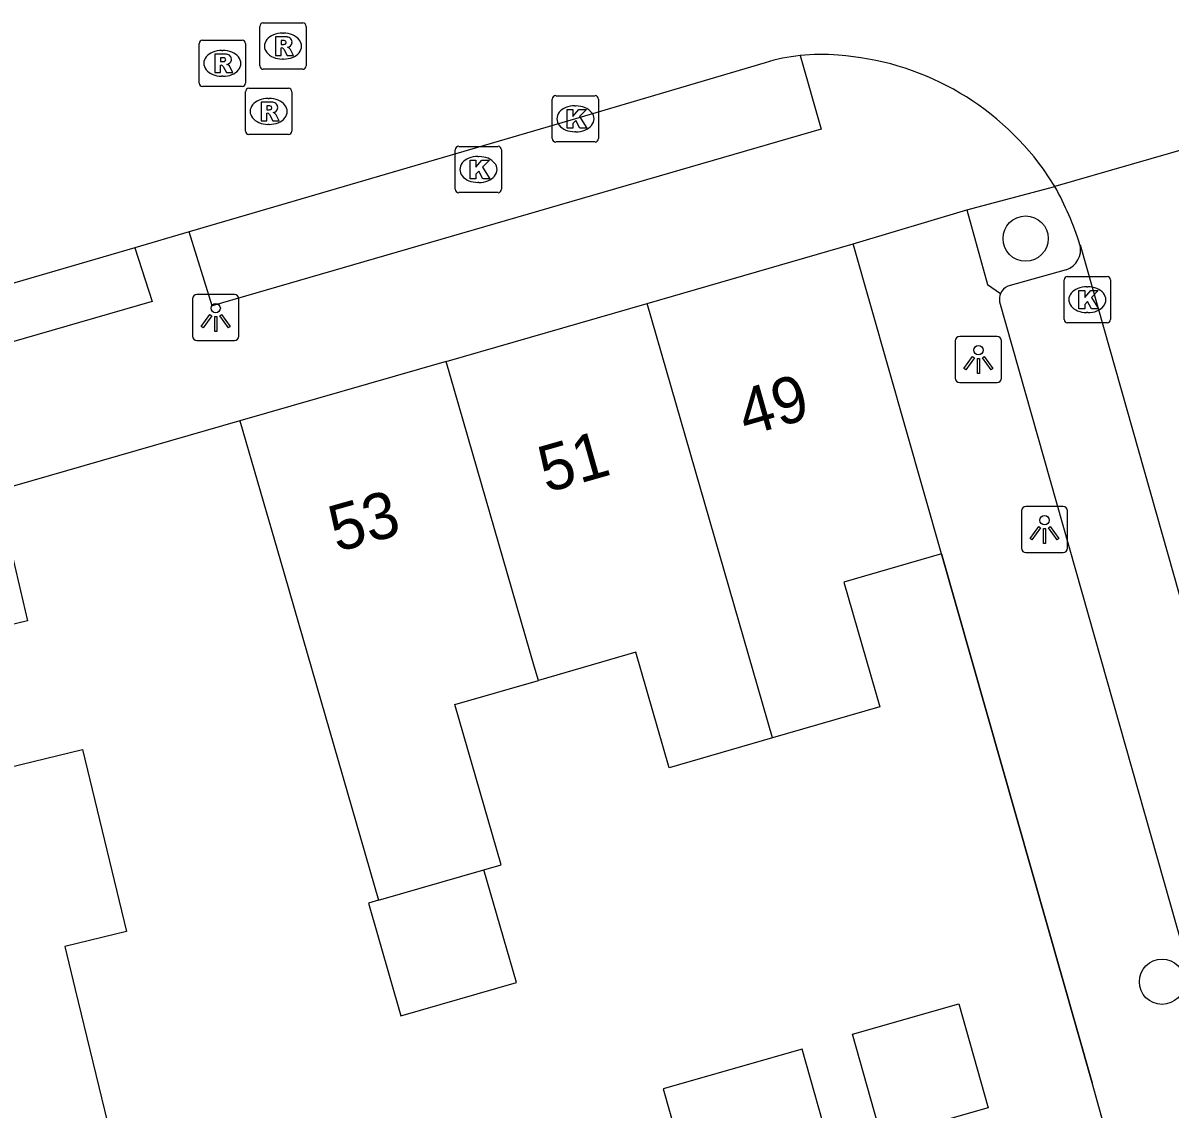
# Model space of a CAD drawing. Extents: x 159718 to 160783, y 383290 to 384030.
# Drawn here: x 160253.65 to 160278.43, y 383556.96 to 383580.41 of the extents above; entities that cross this region are included whole.
import ezdxf

# ---------------------------------------------------------------- set-up
doc = ezdxf.new("R2010")
doc.units = 0
for name, color, linetype in [('IMGEO_Boom', 7, 'Continuous'), ('IMGEO_Kolk', 7, 'Continuous'), ('IMGEO_Lichtpunt', 7, 'Continuous'), ('IMGEO_Muur', 7, 'Continuous'), ('IMGEO_Pand', 7, 'Continuous'), ('IMGEO_Pand_nummerreeks', 7, 'Continuous'), ('IMGEO_Parkeervlak_open', 7, 'Continuous'), ('IMGEO_Rijbaan_lokaal_open', 7, 'Continuous'), ('IMGEO_Rioolput', 7, 'Continuous'), ('IMGEO_Voetpad_open', 7, 'Continuous')]:
    doc.layers.add(name, color=color, linetype=linetype)

msp = doc.modelspace()

# ---------------------------------------------------------------- linework, layer by layer
at = {"layer": 'IMGEO_Boom'}
for centre in [(160275.308, 383575.752), (160278.253, 383559.705)]:
    msp.add_circle(centre, 0.489, dxfattribs=at)
at = {"layer": 'IMGEO_Kolk'}
for p, q in [((160265.083, 383577.911), (160265.083, 383578.763)), ((160265.158, 383578.837), (160266.01, 383578.837)), ((160266.084, 383578.763), (160266.084, 383577.911)), ((160265.571, 383578.617), (160265.596, 383578.617)), ((160265.594, 383578.057), (160265.569, 383578.057)), ((160266.01, 383577.837), (160265.158, 383577.837)), ((160262.988, 383576.817), (160262.988, 383577.669)), ((160263.063, 383577.743), (160263.915, 383577.743)), ((160263.476, 383577.523), (160263.501, 383577.523)), ((160263.989, 383577.669), (160263.989, 383576.817)), ((160263.499, 383576.963), (160263.474, 383576.963)), ((160263.915, 383576.743), (160263.063, 383576.743)), ((160276.139, 383574.006), (160276.139, 383574.858)), ((160276.214, 383574.932), (160277.066, 383574.932)), ((160277.14, 383574.858), (160277.14, 383574.006)), ((160276.627, 383574.712), (160276.652, 383574.712)), ((160276.65, 383574.152), (160276.625, 383574.152)), ((160277.066, 383573.932), (160276.214, 383573.932))]:
    msp.add_line(p, q, dxfattribs=at)
for points in [[(160265.083, 383577.911), (160265.083, 383578.763)], [(160265.158, 383578.837), (160266.01, 383578.837)], [(160266.084, 383578.763), (160266.084, 383577.911)], [(160265.404, 383578.537), (160265.527, 383578.537), (160265.527, 383578.386), (160265.657, 383578.537), (160265.821, 383578.537), (160265.675, 383578.386), (160265.828, 383578.137), (160265.676, 383578.137), (160265.591, 383578.301), (160265.527, 383578.234), (160265.527, 383578.137), (160265.404, 383578.137), (160265.404, 383578.537)], [(160266.01, 383577.837), (160265.158, 383577.837)], [(160262.988, 383576.817), (160262.988, 383577.669)], [(160263.063, 383577.743), (160263.915, 383577.743)], [(160263.989, 383577.669), (160263.989, 383576.817)], [(160263.309, 383577.443), (160263.432, 383577.443), (160263.432, 383577.292), (160263.562, 383577.443), (160263.726, 383577.443), (160263.58, 383577.292), (160263.733, 383577.043), (160263.581, 383577.043), (160263.496, 383577.207), (160263.432, 383577.14), (160263.432, 383577.043), (160263.309, 383577.043), (160263.309, 383577.443)], [(160263.915, 383576.743), (160263.063, 383576.743)], [(160276.139, 383574.006), (160276.139, 383574.858)], [(160276.214, 383574.932), (160277.066, 383574.932)], [(160277.14, 383574.858), (160277.14, 383574.006)], [(160276.46, 383574.632), (160276.583, 383574.632), (160276.583, 383574.481), (160276.713, 383574.632), (160276.877, 383574.632), (160276.731, 383574.481), (160276.884, 383574.232), (160276.732, 383574.232), (160276.647, 383574.396), (160276.583, 383574.329), (160276.583, 383574.232), (160276.46, 383574.232), (160276.46, 383574.632)], [(160277.066, 383573.932), (160276.214, 383573.932)]]:
    msp.add_lwpolyline(points, dxfattribs=at)
for centre, start, end in [((160265.16, 383578.761), 91.552, 178.448), ((160265.16, 383578.761), 91.552, 178.448), ((160266.008, 383578.761), 1.552, 88.448), ((160266.008, 383578.761), 1.552, 88.448), ((160265.16, 383577.913), 181.552, 268.448), ((160265.16, 383577.913), 181.552, 268.448), ((160266.008, 383577.913), 271.552, 358.448), ((160266.008, 383577.913), 271.552, 358.448), ((160263.065, 383577.667), 91.552, 178.448), ((160263.065, 383577.667), 91.552, 178.448), ((160263.913, 383577.667), 1.552, 88.448), ((160263.913, 383577.667), 1.552, 88.448), ((160263.065, 383576.819), 181.552, 268.448), ((160263.065, 383576.819), 181.552, 268.448), ((160263.913, 383576.819), 271.552, 358.448), ((160263.913, 383576.819), 271.552, 358.448), ((160276.216, 383574.856), 91.552, 178.448), ((160276.216, 383574.856), 91.552, 178.448), ((160277.064, 383574.856), 1.552, 88.448), ((160277.064, 383574.856), 1.552, 88.448), ((160276.216, 383574.008), 181.552, 268.448), ((160276.216, 383574.008), 181.552, 268.448), ((160277.064, 383574.008), 271.552, 358.448), ((160277.064, 383574.008), 271.552, 358.448)]:
    msp.add_arc(centre, 0.0765, start, end, dxfattribs=at)
for centre, major_axis, ratio, start_param, end_param in [((160265.57, 383578.337), (-0.387, 0.002), 0.722429, 4.712389, 7.853982), ((160265.595, 383578.337), (-0.39, 0.002), 0.717154, 1.570796, 4.712389), ((160263.475, 383577.243), (-0.387, 0.002), 0.722429, 4.712389, 7.853982), ((160263.5, 383577.243), (-0.39, 0.002), 0.717154, 1.570796, 4.712389), ((160276.626, 383574.432), (-0.387, 0.002), 0.722429, 4.712389, 7.853982), ((160276.651, 383574.432), (-0.39, 0.002), 0.717154, 1.570796, 4.712389)]:
    msp.add_ellipse(centre, major_axis=major_axis, ratio=ratio, start_param=start_param, end_param=end_param, dxfattribs=at)
at = {"layer": 'IMGEO_Lichtpunt'}
for p, q in [((160258.218, 383574.546), (160257.41, 383574.546)), ((160258.218, 383574.546), (160257.41, 383574.546)), ((160257.316, 383574.451), (160257.316, 383573.644)), ((160257.316, 383574.451), (160257.316, 383573.644)), ((160258.312, 383573.644), (160258.312, 383574.451)), ((160258.312, 383573.644), (160258.312, 383574.451)), ((160257.41, 383573.55), (160258.218, 383573.55)), ((160257.41, 383573.55), (160258.218, 383573.55)), ((160273.789, 383573.544), (160273.789, 383572.737)), ((160273.789, 383573.544), (160273.789, 383572.737)), ((160274.691, 383573.639), (160273.883, 383573.639)), ((160274.691, 383573.639), (160273.883, 383573.639)), ((160274.785, 383572.737), (160274.785, 383573.544)), ((160274.785, 383572.737), (160274.785, 383573.544)), ((160273.883, 383572.643), (160274.691, 383572.643)), ((160273.883, 383572.643), (160274.691, 383572.643)), ((160275.217, 383569.872), (160275.217, 383569.065)), ((160275.217, 383569.872), (160275.217, 383569.065)), ((160276.119, 383569.967), (160275.311, 383569.967)), ((160276.119, 383569.967), (160275.311, 383569.967)), ((160276.213, 383569.065), (160276.213, 383569.872)), ((160276.213, 383569.065), (160276.213, 383569.872)), ((160275.311, 383568.971), (160276.119, 383568.971)), ((160275.311, 383568.971), (160276.119, 383568.971))]:
    msp.add_line(p, q, dxfattribs=at)
for points in [[(160257.69, 383574.115), (160257.729, 383574.087), (160257.541, 383573.825), (160257.503, 383573.852), (160257.69, 383574.115)], [(160257.792, 383574.067), (160257.839, 383574.067), (160257.839, 383573.745), (160257.792, 383573.745), (160257.792, 383574.067)], [(160257.902, 383574.087), (160257.94, 383574.114), (160258.127, 383573.852), (160258.088, 383573.824), (160257.902, 383574.087)], [(160274.163, 383573.208), (160274.202, 383573.18), (160274.014, 383572.918), (160273.976, 383572.945), (160274.163, 383573.208)], [(160274.265, 383573.16), (160274.312, 383573.16), (160274.312, 383572.838), (160274.265, 383572.838), (160274.265, 383573.16)], [(160274.375, 383573.18), (160274.413, 383573.207), (160274.6, 383572.945), (160274.561, 383572.917), (160274.375, 383573.18)], [(160275.591, 383569.536), (160275.63, 383569.508), (160275.442, 383569.246), (160275.404, 383569.273), (160275.591, 383569.536)], [(160275.693, 383569.488), (160275.74, 383569.488), (160275.74, 383569.166), (160275.693, 383569.166), (160275.693, 383569.488)], [(160275.803, 383569.508), (160275.841, 383569.535), (160276.028, 383569.273), (160275.989, 383569.245), (160275.803, 383569.508)]]:
    msp.add_lwpolyline(points, dxfattribs=at)
for centre in [(160257.815, 383574.249), (160274.288, 383573.342), (160275.716, 383569.67)]:
    msp.add_circle(centre, 0.0994, dxfattribs=at)
for centre, start, end in [((160257.41, 383574.451), 90, 180), ((160257.41, 383574.451), 90, 180), ((160258.218, 383574.451), 0, 90), ((160258.218, 383574.451), 0, 90), ((160257.41, 383573.644), 180, 270), ((160257.41, 383573.644), 180, 270), ((160258.218, 383573.644), 270, 0), ((160258.218, 383573.644), 270, 360), ((160273.883, 383573.544), 90, 180), ((160273.883, 383573.544), 90, 180), ((160274.691, 383573.544), 0, 90), ((160274.691, 383573.544), 0, 90), ((160273.883, 383572.737), 180, 270), ((160273.883, 383572.737), 180, 270), ((160274.691, 383572.737), 270, 0), ((160274.691, 383572.737), 270, 360), ((160275.311, 383569.872), 90, 180), ((160275.311, 383569.872), 90, 180), ((160276.119, 383569.872), 0, 90), ((160276.119, 383569.872), 0, 90), ((160275.311, 383569.065), 180, 270), ((160275.311, 383569.065), 180, 270), ((160276.119, 383569.065), 270, 0), ((160276.119, 383569.065), 270, 360)]:
    msp.add_arc(centre, 0.0946, start, end, dxfattribs=at)
at = {"layer": 'IMGEO_Muur'}
msp.add_lwpolyline([(160273.488, 383568.945), (160276.741, 383557.524)], dxfattribs=at)
at = {"layer": 'IMGEO_Pand'}
for points in [[(160267.131, 383574.352), (160271.583, 383575.638)], [(160273.488, 383568.945), (160271.583, 383575.638)], [(160262.793, 383573.1), (160267.131, 383574.352)], [(160269.84, 383564.97), (160267.131, 383574.352)], [(160262.793, 383573.1), (160258.339, 383571.813)], [(160264.783, 383566.21), (160264.693, 383566.52), (160262.793, 383573.1)], [(160258.339, 383571.813), (160259.212, 383568.791), (160261.327, 383561.466)], [(160273.488, 383568.945), (160271.382, 383568.331), (160272.16, 383565.64), (160269.84, 383564.97)], [(160269.84, 383564.97), (160267.609, 383564.325), (160266.888, 383566.818), (160264.783, 383566.21)], [(160263.607, 383562.124), (160263.98, 383562.232), (160262.981, 383565.69), (160264.783, 383566.21)], [(160247.938, 383563.021), (160253.602, 383564.398), (160254.936, 383564.722), (160255.889, 383560.792), (160254.554, 383560.468), (160254.781, 383559.534), (160255.541, 383556.399), (160249.88, 383555.027)], [(160261.327, 383561.466), (160261.114, 383561.405), (160261.816, 383558.972), (160264.309, 383559.691), (160263.607, 383562.124)], [(160261.327, 383561.466), (160263.607, 383562.124)], [(160272.203, 383556.33), (160271.566, 383558.576), (160273.863, 383559.227), (160274.5, 383556.981), (160272.203, 383556.33)], [(160268.108, 383555.181), (160271.109, 383556.033), (160270.481, 383558.247), (160267.48, 383557.396), (160268.108, 383555.181)]]:
    msp.add_lwpolyline(points, dxfattribs=at)
at = {"layer": 'IMGEO_Parkeervlak_open'}
msp.add_lwpolyline([(160276.181, 383575.08), (160274.921, 383574.725)], dxfattribs=at)
for centre, radius, start, end in [((160276.04, 383575.512), 0.455, 288.1084, 13.3484), ((160275.053, 383574.444), 0.311, 115.1578, 157.0315)]:
    msp.add_arc(centre, radius, start, end, dxfattribs=at)
at = {"layer": 'IMGEO_Rijbaan_lokaal_open'}
for points in [[(160269.683, 383579.549), (160265.584, 383578.337), (160257.241, 383575.894)], [(160279.234, 383577.826), (160275.937, 383576.879)], [(160275.937, 383576.879), (160275.692, 383577.25)], [(160257.241, 383575.894), (160256.071, 383575.553)], [(160256.071, 383575.553), (160251.743, 383574.293)], [(160276.482, 383575.617), (160281.507, 383557.891)]]:
    msp.add_lwpolyline(points, dxfattribs=at)
for centre, radius, start, end in [((160270.895, 383575.559), 4.17, 96.2987, 106.9044), ((160270.877, 383575.725), 4.003, 84.5477, 96.2918), ((160270.856, 383573.759), 5.964, 35.8232, 86.1444), ((160269.885, 383573.517), 6.923, 17.6598, 29.0548)]:
    msp.add_arc(centre, radius, start, end, dxfattribs=at)
at = {"layer": 'IMGEO_Rioolput'}
for p, q in [((160258.766, 383579.481), (160258.766, 383580.333)), ((160258.841, 383580.407), (160259.693, 383580.407)), ((160259.767, 383580.333), (160259.767, 383579.481)), ((160257.532, 383580.035), (160258.384, 383580.035)), ((160259.254, 383580.187), (160259.279, 383580.187)), ((160257.457, 383579.109), (160257.457, 383579.961)), ((160257.945, 383579.815), (160257.97, 383579.815)), ((160258.458, 383579.961), (160258.458, 383579.109)), ((160259.277, 383579.627), (160259.252, 383579.627)), ((160257.968, 383579.255), (160257.943, 383579.255)), ((160259.693, 383579.407), (160258.841, 383579.407)), ((160258.384, 383579.035), (160257.532, 383579.035)), ((160258.532, 383578.997), (160259.384, 383578.997)), ((160258.457, 383578.071), (160258.457, 383578.923)), ((160258.945, 383578.777), (160258.97, 383578.777)), ((160259.458, 383578.923), (160259.458, 383578.071)), ((160258.968, 383578.217), (160258.943, 383578.217)), ((160259.384, 383577.997), (160258.532, 383577.997))]:
    msp.add_line(p, q, dxfattribs=at)
for points in [[(160258.766, 383579.481), (160258.766, 383580.333)], [(160258.841, 383580.407), (160259.693, 383580.407)], [(160259.767, 383580.333), (160259.767, 383579.481)], [(160257.532, 383580.035), (160258.384, 383580.035)], [(160259.355, 383580.105), (160259.103, 383580.107), (160259.103, 383579.707)], [(160259.281, 383580.026), (160259.227, 383580.026), (160259.227, 383579.945)], [(160257.457, 383579.109), (160257.457, 383579.961)], [(160258.046, 383579.733), (160257.794, 383579.735), (160257.794, 383579.335)], [(160258.458, 383579.961), (160258.458, 383579.109)], [(160259.103, 383579.707), (160259.227, 383579.707), (160259.227, 383579.869), (160259.238, 383579.869)], [(160259.227, 383579.945), (160259.279, 383579.945)], [(160259.285, 383579.84), (160259.356, 383579.707), (160259.496, 383579.707), (160259.431, 383579.833)], [(160257.794, 383579.335), (160257.918, 383579.335), (160257.918, 383579.497), (160257.929, 383579.497)], [(160257.972, 383579.654), (160257.918, 383579.654), (160257.918, 383579.573)], [(160257.918, 383579.573), (160257.97, 383579.573)], [(160257.976, 383579.468), (160258.047, 383579.335), (160258.187, 383579.335), (160258.122, 383579.461)], [(160259.693, 383579.407), (160258.841, 383579.407)], [(160258.384, 383579.035), (160257.532, 383579.035)], [(160258.532, 383578.997), (160259.384, 383578.997)], [(160258.457, 383578.071), (160258.457, 383578.923)], [(160259.458, 383578.923), (160259.458, 383578.071)], [(160259.046, 383578.695), (160258.794, 383578.697), (160258.794, 383578.297)], [(160258.972, 383578.616), (160258.918, 383578.616), (160258.918, 383578.535)], [(160258.918, 383578.535), (160258.97, 383578.535)], [(160258.794, 383578.297), (160258.918, 383578.297), (160258.918, 383578.459), (160258.929, 383578.459)], [(160258.976, 383578.43), (160259.047, 383578.297), (160259.187, 383578.297), (160259.122, 383578.423)], [(160259.384, 383577.997), (160258.532, 383577.997)]]:
    msp.add_lwpolyline(points, dxfattribs=at)
for centre, radius, start, end in [((160258.843, 383580.331), 0.0765, 91.552, 178.448), ((160258.843, 383580.331), 0.0765, 91.552, 178.448), ((160259.691, 383580.331), 0.0765, 1.552, 88.448), ((160259.691, 383580.331), 0.0765, 1.552, 88.448), ((160257.534, 383579.959), 0.0765, 91.552, 178.448), ((160257.534, 383579.959), 0.0765, 91.552, 178.448), ((160258.382, 383579.959), 0.0765, 1.552, 88.448), ((160258.382, 383579.959), 0.0765, 1.552, 88.448), ((160259.287, 383579.93), 0.0964, 77.0061, 93.1865), ((160259.301, 383579.987), 0.0378, 276.6634, 79.6772), ((160259.354, 383579.995), 0.109, 350.3612, 89.416), ((160258.045, 383579.623), 0.109, 350.3612, 89.416), ((160259.237, 383579.816), 0.0533, 26.0293, 88.6989), ((160259.263, 383580.134), 0.19, 274.7715, 282.9687), ((160259.352, 383579.995), 0.112, 277.5842, 350.9817), ((160259.336, 383579.78), 0.108, 29.5134, 73.7905), ((160257.928, 383579.444), 0.0533, 26.0293, 88.6989), ((160257.954, 383579.762), 0.19, 274.7715, 282.9687), ((160257.978, 383579.558), 0.0964, 77.0061, 93.1865), ((160257.992, 383579.615), 0.0378, 276.6634, 79.6772), ((160258.043, 383579.623), 0.112, 277.5842, 350.9817), ((160258.027, 383579.408), 0.108, 29.5134, 73.7905), ((160258.843, 383579.483), 0.0765, 181.552, 268.448), ((160258.843, 383579.483), 0.0765, 181.552, 268.448), ((160259.691, 383579.483), 0.0765, 271.552, 358.448), ((160259.691, 383579.483), 0.0765, 271.552, 358.448), ((160257.534, 383579.111), 0.0765, 181.552, 268.448), ((160257.534, 383579.111), 0.0765, 181.552, 268.448), ((160258.382, 383579.111), 0.0765, 271.552, 358.448), ((160258.382, 383579.111), 0.0765, 271.552, 358.448), ((160258.534, 383578.921), 0.0765, 91.552, 178.448), ((160258.534, 383578.921), 0.0765, 91.552, 178.448), ((160259.382, 383578.921), 0.0765, 1.552, 88.448), ((160259.382, 383578.921), 0.0765, 1.552, 88.448), ((160258.954, 383578.724), 0.19, 274.7715, 282.9687), ((160258.978, 383578.52), 0.0964, 77.0061, 93.1865), ((160258.992, 383578.577), 0.0378, 276.6634, 79.6772), ((160259.045, 383578.585), 0.109, 350.3612, 89.416), ((160259.043, 383578.585), 0.112, 277.5842, 350.9817), ((160258.928, 383578.406), 0.0533, 26.0293, 88.6989), ((160259.027, 383578.37), 0.108, 29.5134, 73.7905), ((160258.534, 383578.073), 0.0765, 181.552, 268.448), ((160258.534, 383578.073), 0.0765, 181.552, 268.448), ((160259.382, 383578.073), 0.0765, 271.552, 358.448), ((160259.382, 383578.073), 0.0765, 271.552, 358.448)]:
    msp.add_arc(centre, radius, start, end, dxfattribs=at)
for centre, major_axis, ratio, start_param, end_param in [((160259.253, 383579.907), (-0.387, 0.002), 0.722429, 4.712389, 7.853982), ((160259.278, 383579.907), (-0.39, 0.002), 0.717154, 1.570796, 4.712389), ((160257.944, 383579.535), (-0.387, 0.002), 0.722429, 4.712389, 7.853982), ((160257.969, 383579.535), (-0.39, 0.002), 0.717154, 1.570796, 4.712389), ((160258.944, 383578.497), (-0.387, 0.002), 0.722429, 4.712389, 7.853982), ((160258.969, 383578.497), (-0.39, 0.002), 0.717154, 1.570796, 4.712389)]:
    msp.add_ellipse(centre, major_axis=major_axis, ratio=ratio, start_param=start_param, end_param=end_param, dxfattribs=at)
at = {"layer": 'IMGEO_Voetpad_open'}
for points in [[(160270.438, 383579.704), (160270.889, 383578.115), (160257.741, 383574.301), (160257.241, 383575.894)], [(160274.036, 383576.37), (160275.937, 383576.879)], [(160271.583, 383575.638), (160274.036, 383576.37)], [(160274.036, 383576.37), (160274.482, 383574.759), (160274.767, 383574.565)], [(160256.071, 383575.553), (160256.439, 383574.395), (160252.103, 383573.137), (160251.743, 383574.293)], [(160274.746, 383574.386), (160279.377, 383558.042)], [(160258.339, 383571.813), (160253.089, 383570.307), (160253.749, 383567.499), (160219.583, 383559.225)], [(160277.064, 383556.388), (160276.741, 383557.524), (160273.488, 383568.945)]]:
    msp.add_lwpolyline(points, dxfattribs=at)
msp.add_arc((160275.047, 383574.441), 0.306, 156.1654, 190.452, dxfattribs=at)

# ---------------------------------------------------------------- texts
at = {"layer": 'IMGEO_Pand_nummerreeks'}
for s, p in [('49', (160269.268, 383571.48)), ('51', (160264.958, 383570.258)), ('53', (160260.432, 383568.974))]:
    msp.add_text(s, height=1, rotation=15.8366, dxfattribs=at).set_placement(p)

doc.saveas('drawing.dxf')
